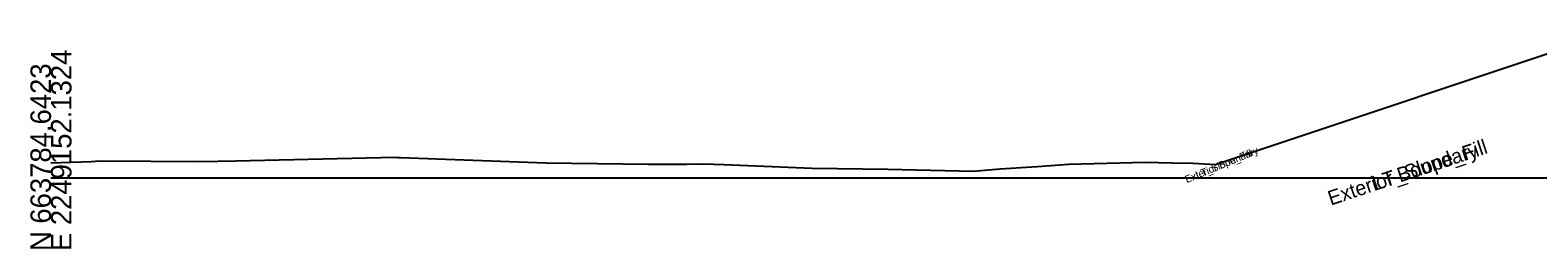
# Model space of a CAD drawing. Extents: x -26 to 2603, y -10 to 9566.
# Drawn here: x 997.2 to 1203, y 7490.3 to 7520.1 of the extents above; entities that cross this region are included whole.
import ezdxf

# ---------------------------------------------------------------- set-up
doc = ezdxf.new("R2010")
doc.units = 0
for name, color, linetype in [('Default', 7, 'Continuous'), ('Exist Cross Section Cell', 7, 'Continuous'), ('Exist XS Ground Line', 7, 'Continuous'), ('Scratch_Level_9', 7, 'Continuous')]:
    doc.layers.add(name, color=color, linetype=linetype)

msp = doc.modelspace()

# ---------------------------------------------------------------- linework, layer by layer
at = {"layer": 'Exist Cross Section Cell'}
msp.add_line((1000, 7500), (1300, 7500), dxfattribs=at)
at = {"layer": 'Exist XS Ground Line'}
for p, q in [((1000, 7502.03), (1005.5, 7502.24)), ((1005.5, 7502.24), (1006.1, 7502.29)), ((1006.1, 7502.29), (1007.01, 7502.3)), ((1007.01, 7502.3), (1020.26, 7502.23)), ((1020.26, 7502.23), (1025.22, 7502.33)), ((1025.22, 7502.33), (1046.98, 7502.81)), ((1046.98, 7502.81), (1047.33, 7502.79)), ((1047.33, 7502.79), (1047.73, 7502.78)), ((1047.73, 7502.78), (1067.58, 7502.02)), ((1067.58, 7502.02), (1081.58, 7501.86)), ((1081.58, 7501.86), (1086.81, 7501.86)), ((1086.81, 7501.86), (1089.1, 7501.9)), ((1089.1, 7501.9), (1091.86, 7501.82)), ((1091.86, 7501.82), (1103.95, 7501.3)), ((1103.95, 7501.3), (1114.26, 7501.17)), ((1125.92, 7500.9), (1129.62, 7501.24)), ((1129.62, 7501.24), (1134.66, 7501.52)), ((1134.66, 7501.52), (1138.98, 7501.86)), ((1138.98, 7501.86), (1149.4, 7502.15)), ((1149.4, 7502.15), (1153.02, 7502.04)), ((1153.02, 7502.04), (1155.92, 7502)), ((1155.92, 7502), (1159.08, 7501.82)), ((1114.26, 7501.17), (1125.92, 7500.9))]:
    msp.add_line(p, q, dxfattribs=at)
msp.add_lwpolyline([(1214.05, 7520.14), (1159.08, 7501.82)], dxfattribs=at)

# ---------------------------------------------------------------- texts
at = {"layer": 'Default'}
msp.add_text('-', height=0.0001, dxfattribs=at).set_placement((1000, 7500))
msp.add_text('-', height=0.0001, dxfattribs=at).set_placement((1000, 7500))
msp.add_text('-', height=0.0001, dxfattribs=at).set_placement((1000, 7500))
msp.add_text('-', height=0.0001, dxfattribs=at).set_placement((1000, 7500))
msp.add_text('-', height=0.0001, dxfattribs=at).set_placement((1000, 7500))
at = {"layer": 'Exist Cross Section Cell'}
for s, p in [('E 2249152.1324', (1002.8, 7490)), ('N 663784.6423', (1000, 7490))]:
    msp.add_text(s, height=2.8, rotation=90, dxfattribs=at).set_placement(p)
at = {"layer": 'Scratch_Level_9'}
for s, height, rotation, p in [('LT_Slope_Fill', 2, 18.4332, (1180.79, 7498.22)), ('LT_Slope_Fill', 2, 18.4332, (1180.79, 7498.22)), ('Exterior Boundary', 1, 22.5575, (1155.08, 7499.26)), ('LT_Slope_Fill', 1, 22.5575, (1156.54, 7499.86)), ('Exterior Boundary', 2, 18.4332, (1174.74, 7496.2)), ('Exterior Boundary', 2, 18.4332, (1174.74, 7496.2))]:
    msp.add_text(s, height=height, rotation=rotation, dxfattribs=at).set_placement(p)

doc.saveas('drawing.dxf')
